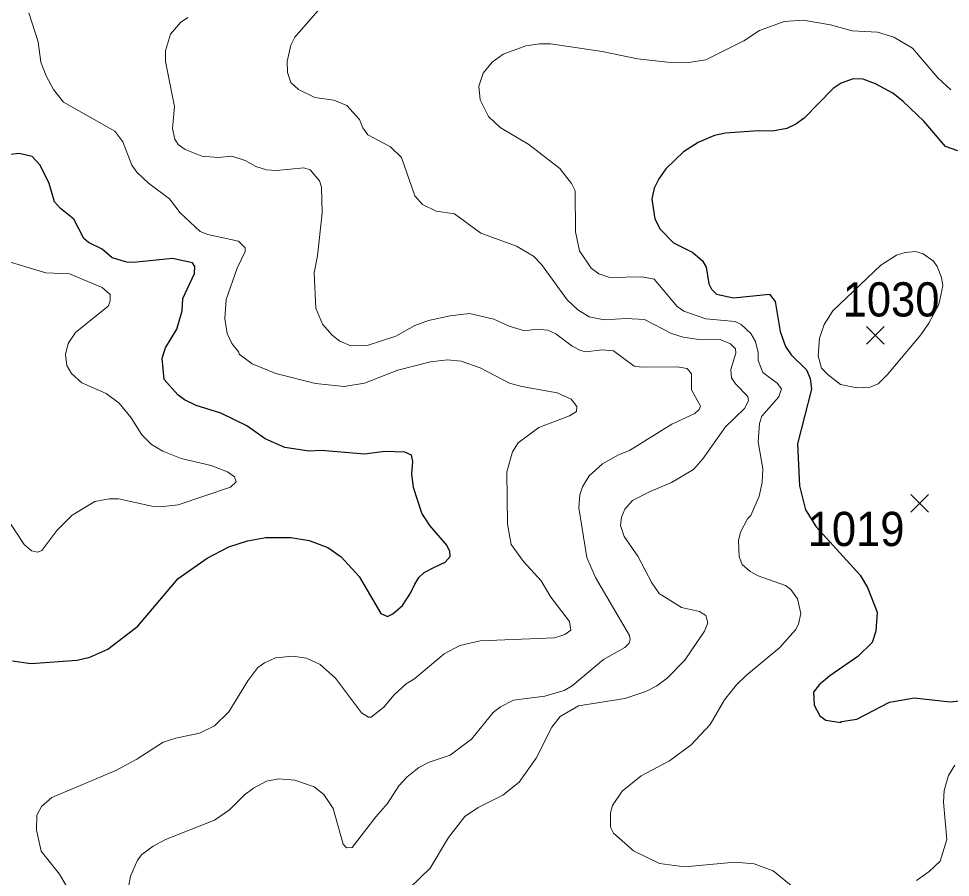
# Model space of a CAD drawing. Extents: x 265 to 291.4, y 7731.5 to 7759.6.
# Drawn here: x 266.78 to 268.956, y 7750.96 to 7752.966 of the extents above; entities that cross this region are included whole.
import ezdxf
from ezdxf.enums import TextEntityAlignment as Align

# ---------------------------------------------------------------- set-up
doc = ezdxf.new("R2010")
doc.units = 0
doc.header["$LTSCALE"] = 0.032
for name, color, linetype, lineweight in [('1', 7, 'Continuous', 25), ('2', 7, 'Continuous', 13), ('21', 7, 'Continuous', 25), ('61', 7, 'Continuous', 13)]:
    doc.layers.add(name, color=color, linetype=linetype, lineweight=lineweight)

msp = doc.modelspace()

# ---------------------------------------------------------------- linework, layer by layer
at = {"layer": '1'}
for points in [[(268.9733, 7752.657), (268.9447, 7752.6674), (268.8938, 7752.7262), (268.846, 7752.7724), (268.8214, 7752.7915), (268.7816, 7752.8137), (268.7522, 7752.8241), (268.7291, 7752.8256), (268.7013, 7752.8153), (268.6822, 7752.8026), (268.6146, 7752.7334), (268.5955, 7752.7191), (268.574, 7752.7095), (268.5406, 7752.7031), (268.5072, 7752.7039), (268.4308, 7752.6984), (268.4054, 7752.6928), (268.3672, 7752.6769), (268.333, 7752.6546), (268.2916, 7752.6148), (268.2749, 7752.5918), (268.2645, 7752.5695), (268.259, 7752.5441), (268.2661, 7752.4979), (268.2781, 7752.4741), (268.3091, 7752.4422), (268.3545, 7752.42), (268.3775, 7752.4001), (268.3855, 7752.385), (268.3918, 7752.3468), (268.3982, 7752.3341), (268.4101, 7752.3221), (268.4499, 7752.3134), (268.5334, 7752.3221), (268.5469, 7752.3054), (268.5589, 7752.2354), (268.5708, 7752.2004), (268.5843, 7752.1805), (268.6201, 7752.1455), (268.6289, 7752.1256), (268.6321, 7752.1002), (268.5994, 7751.9729), (268.6034, 7751.8743), (268.6174, 7751.819), (268.643, 7751.7791), (268.7458, 7751.6659), (268.7625, 7751.6372), (268.7848, 7751.5799), (268.7824, 7751.5354), (268.7736, 7751.5091), (268.7403, 7751.4757), (268.6742, 7751.4312), (268.6496, 7751.4097), (268.6368, 7751.393), (268.6376, 7751.3627), (268.6511, 7751.3373), (268.6655, 7751.327), (268.7005, 7751.3222), (268.7021, 7751.3246), (268.7379, 7751.3301), (268.8142, 7751.3691), (268.8715, 7751.3795), (268.9558, 7751.3699), (268.99, 7751.3739)], [(267.1859, 7752.3953), (267.139, 7752.4056), (267.0483, 7752.3961), (267.0324, 7752.3969), (266.9981, 7752.4072), (266.9751, 7752.4271), (266.9433, 7752.443), (266.9321, 7752.4526), (266.909, 7752.4971), (266.8772, 7752.5226), (266.8637, 7752.5377), (266.851, 7752.5807), (266.8303, 7752.6236), (266.8112, 7752.6435), (266.781, 7752.6506), (266.6983, 7752.6411)], [(267.123, 7752.1972), (267.1493, 7752.2402), (267.162, 7752.2832), (267.1636, 7752.3118), (267.1906, 7752.3707), (267.1914, 7752.3866), (267.1859, 7752.3953)], [(266.7651, 7751.4662), (266.808, 7751.4598), (266.9162, 7751.4678), (266.9464, 7751.4749), (266.9878, 7751.4932), (267.0586, 7751.5473), (267.1525, 7751.6579), (267.2201, 7751.7056), (267.271, 7751.7319), (267.314, 7751.7462), (267.3569, 7751.7541), (267.4158, 7751.7541), (267.4587, 7751.747), (267.5017, 7751.7303), (267.5335, 7751.7088), (267.5749, 7751.6627), (267.6256, 7751.5766), (267.6411, 7751.5698), (267.654, 7751.5755), (267.6767, 7751.5951), (267.6948, 7751.6241), (267.7051, 7751.6447), (267.7144, 7751.6607), (267.7268, 7751.6726), (267.751, 7751.685), (267.7763, 7751.6963), (267.7881, 7751.7096), (267.7873, 7751.7215), (267.7801, 7751.7359), (267.7403, 7751.782), (267.7212, 7751.8106), (267.7021, 7751.8711), (267.6982, 7751.9029), (267.7005, 7751.9316), (267.6974, 7751.9459), (267.6815, 7751.953), (267.6353, 7751.9546), (267.5876, 7751.949), (267.4874, 7751.957), (267.4587, 7751.9554), (267.4015, 7751.9641), (267.3553, 7751.9848), (267.3131, 7752.0151), (267.2519, 7752.0445), (267.1946, 7752.062), (267.1676, 7752.0755), (267.1517, 7752.0874), (267.1198, 7752.1232), (267.1151, 7752.1726), (267.123, 7752.1972)]]:
    msp.add_lwpolyline(points, dxfattribs=at)
at = {"layer": '2'}
for points in [[(267.407, 7752.8654), (267.4158, 7752.9036), (267.4253, 7752.9227), (267.4842, 7752.9903)], [(267.3251, 7752.1598), (267.2949, 7752.1821), (267.2941, 7752.1869), (267.2774, 7752.2068), (267.267, 7752.2307), (267.2615, 7752.2657), (267.2646, 7752.3102), (267.2901, 7752.3834), (267.3092, 7752.4216), (267.3092, 7752.4303), (267.2933, 7752.4462), (267.2217, 7752.4613), (267.2042, 7752.4685), (267.1572, 7752.5122), (267.1318, 7752.5449), (267.0833, 7752.5814), (267.0562, 7752.6069), (267.0443, 7752.6236), (267.0228, 7752.6777), (267.0045, 7752.7032), (266.8844, 7752.7708), (266.8613, 7752.8002), (266.8438, 7752.832), (266.8319, 7752.8639), (266.8255, 7752.9116), (266.8033, 7752.9792)], [(267.446, 7752.6172), (267.3824, 7752.6109), (267.3585, 7752.6125), (267.3338, 7752.6204), (267.3092, 7752.6347), (267.2774, 7752.6443), (267.2456, 7752.6411), (267.2074, 7752.6443), (267.1684, 7752.6602), (267.1525, 7752.6721), (267.1445, 7752.6841), (267.1389, 7752.7095), (267.1437, 7752.7604), (267.123, 7752.8654), (267.123, 7752.8909), (267.1342, 7752.9299), (267.158, 7752.9569), (267.1747, 7752.9681)], [(268.1619, 7751.1106), (268.1667, 7751.1281), (268.1898, 7751.1615), (268.2335, 7751.1973), (268.3004, 7751.2323), (268.3505, 7751.2697), (268.395, 7751.3174), (268.4284, 7751.3747), (268.4563, 7751.4097), (268.4801, 7751.4328), (268.5581, 7751.4972), (268.5947, 7751.5386), (268.601, 7751.5513), (268.6066, 7751.5768), (268.5994, 7751.611), (268.5835, 7751.6324), (268.5708, 7751.642), (268.5072, 7751.6643), (268.4881, 7751.6746), (268.4698, 7751.6913), (268.4626, 7751.7088), (268.461, 7751.747), (268.4658, 7751.7661), (268.4825, 7751.7979), (268.4897, 7751.805), (268.5096, 7751.8504), (268.5167, 7751.8822), (268.5183, 7751.914), (268.5072, 7751.9777), (268.5104, 7752.0206), (268.5159, 7752.0373), (268.5557, 7752.0827), (268.5613, 7752.101), (268.5517, 7752.1145), (268.5183, 7752.1392), (268.5072, 7752.167), (268.5072, 7752.1861), (268.5008, 7752.2116), (268.4897, 7752.2307), (268.4674, 7752.2513), (268.4531, 7752.2585), (268.3847, 7752.2648), (268.3338, 7752.2823), (268.3178, 7752.2935), (268.2646, 7752.3571), (268.2351, 7752.3627), (268.1604, 7752.3611), (268.1349, 7752.3698), (268.1174, 7752.3834), (268.0895, 7752.4232), (268.0808, 7752.4677), (268.08, 7752.5639), (268.0713, 7752.5807), (268.0442, 7752.6157), (267.9718, 7752.6721), (267.9042, 7752.7119), (267.8772, 7752.7374), (267.8581, 7752.7764), (267.8549, 7752.8082), (267.8652, 7752.8384), (267.8859, 7752.8638), (267.9114, 7752.8829), (267.9647, 7752.902), (267.9965, 7752.9068), (268.0219, 7752.9068), (268.1429, 7752.8893), (268.2256, 7752.8718), (268.2956, 7752.8638), (268.3401, 7752.8623), (268.3847, 7752.8694), (268.4738, 7752.914), (268.5104, 7752.9378), (268.5676, 7752.9593), (268.6122, 7752.9625), (268.6758, 7752.9514), (268.7267, 7752.937), (268.7856, 7752.9339), (268.8238, 7752.9227), (268.8675, 7752.8965), (268.9272, 7752.8273), (268.9574, 7752.7994)], [(267.5462, 7752.7628), (267.516, 7752.7756), (267.4715, 7752.7819), (267.4333, 7752.8002), (267.4158, 7752.8169), (267.4078, 7752.84), (267.407, 7752.8654)], [(267.6934, 7750.9356), (267.7411, 7750.9817), (267.7841, 7751.0533), (267.8223, 7751.1027), (267.8533, 7751.1233), (267.9106, 7751.152), (267.9488, 7751.1822), (267.9885, 7751.2387), (268.0251, 7751.3111), (268.045, 7751.3357), (268.0872, 7751.3612), (268.1954, 7751.3779), (268.2447, 7751.3946), (268.2701, 7751.4073), (268.2948, 7751.4256), (268.3362, 7751.4678), (268.3815, 7751.5354), (268.3894, 7751.5545), (268.3847, 7751.572), (268.3704, 7751.5815), (268.3282, 7751.5903), (268.2757, 7751.6229), (268.259, 7751.6484), (268.2264, 7751.7104), (268.1938, 7751.7565), (268.1858, 7751.782), (268.1882, 7751.8011), (268.1961, 7751.8202), (268.2137, 7751.8401), (268.255, 7751.8615), (268.3051, 7751.8822), (268.356, 7751.9132), (268.3783, 7751.9379), (268.4308, 7752.0127), (268.4754, 7752.0556), (268.4849, 7752.0731), (268.4833, 7752.0835), (268.4539, 7752.1129), (268.4451, 7752.1272), (268.4435, 7752.1463), (268.4547, 7752.1845), (268.4539, 7752.1948), (268.4427, 7752.206), (268.4197, 7752.2155), (268.3688, 7752.2163), (268.3322, 7752.2219), (268.3051, 7752.2306), (268.2415, 7752.2633), (268.1985, 7752.2656), (268.1476, 7752.2625), (268.1126, 7752.2696), (268.0856, 7752.2855), (268.0609, 7752.3094), (268.0012, 7752.3913), (267.9822, 7752.4112), (267.9424, 7752.4343), (267.8597, 7752.4645), (267.7976, 7752.5099), (267.7547, 7752.5162), (267.7228, 7752.5321), (267.7053, 7752.552), (267.6743, 7752.6411), (267.6481, 7752.6666), (267.5955, 7752.6944), (267.5836, 7752.7111), (267.5757, 7752.7302), (267.5462, 7752.7628)], [(267.4699, 7752.3722), (267.4778, 7752.412), (267.489, 7752.5123), (267.4874, 7752.5719), (267.4826, 7752.587), (267.4611, 7752.6125), (267.446, 7752.6172)], [(266.7476, 7752.4009), (266.843, 7752.3722), (266.8987, 7752.3699), (266.9751, 7752.338), (266.9934, 7752.3213), (266.9934, 7752.3062), (266.9886, 7752.2943), (266.913, 7752.233), (266.8955, 7752.2068), (266.8892, 7752.1813), (266.8923, 7752.1559), (266.9035, 7752.1368), (266.9274, 7752.1153), (266.9846, 7752.0906), (267.0149, 7752.0676), (267.0427, 7752.0334)], [(267.0363, 7750.9372), (267.0411, 7750.9627), (267.0578, 7751.0008), (267.0674, 7751.0136), (267.0944, 7751.0334), (267.123, 7751.0486), (267.2376, 7751.0939), (267.2726, 7751.1177), (267.3076, 7751.1528), (267.3283, 7751.1687), (267.3585, 7751.1846), (267.3871, 7751.1901), (267.4253, 7751.187), (267.4699, 7751.1718), (267.4929, 7751.1536), (267.5144, 7751.1209), (267.5375, 7751.0374), (267.5454, 7751.0295), (267.559, 7751.0303), (267.6138, 7751.1019), (267.6417, 7751.1329), (267.6679, 7751.1742), (267.687, 7751.1949), (267.7149, 7751.2172), (267.7388, 7751.2291), (267.7881, 7751.2458), (267.8374, 7751.2832), (267.8883, 7751.3453), (267.905, 7751.3588), (267.936, 7751.3739), (268.0092, 7751.3834), (268.0538, 7751.397), (268.0729, 7751.4073), (268.146, 7751.4694), (268.1954, 7751.4972), (268.2057, 7751.5075), (268.2081, 7751.5147), (268.2065, 7751.5251), (268.1269, 7751.6603), (268.1071, 7751.7072), (268.088, 7751.8234), (268.0903, 7751.8536), (268.0967, 7751.8727), (268.1126, 7751.8981), (268.1436, 7751.926), (268.181, 7751.9467), (268.2065, 7751.957), (268.3059, 7752.019), (268.3592, 7752.0437), (268.3696, 7752.0532), (268.3727, 7752.0604), (268.3513, 7752.0986), (268.3513, 7752.136), (268.3417, 7752.1487), (268.3179, 7752.1527), (268.2351, 7752.1519), (268.2176, 7752.1543), (268.1691, 7752.1901), (268.1429, 7752.1925), (268.1047, 7752.1877), (268.0919, 7752.1909), (268.0729, 7752.2012), (268.0347, 7752.2298), (268.0156, 7752.2386), (267.9901, 7752.2402), (267.9615, 7752.237), (267.9257, 7752.2473), (267.8899, 7752.2641), (267.8326, 7752.2768), (267.7881, 7752.272), (267.7372, 7752.2609), (267.7053, 7752.2489), (267.6608, 7752.2243), (267.594, 7752.2028), (267.5558, 7752.202), (267.5303, 7752.2123), (267.512, 7752.2267), (267.4898, 7752.2521), (267.4738, 7752.2895), (267.4699, 7752.3722)], [(266.9035, 7750.9197), (266.8756, 7750.9674), (266.8327, 7751.0215), (266.8215, 7751.0708), (266.8223, 7751.1058), (266.8335, 7751.1257), (266.8574, 7751.1464), (267.0069, 7751.21), (267.0562, 7751.2363), (267.1175, 7751.2761), (267.1469, 7751.2856), (267.2026, 7751.2967), (267.2376, 7751.3142), (267.271, 7751.3469), (267.3155, 7751.4193), (267.3386, 7751.4503), (267.3537, 7751.4614), (267.38, 7751.4733), (267.4206, 7751.4765), (267.4524, 7751.4725), (267.4842, 7751.4574), (267.52, 7751.4256), (267.5804, 7751.3445), (267.5972, 7751.3341), (267.6035, 7751.3341), (267.6329, 7751.358), (267.6568, 7751.3866), (267.6847, 7751.4121), (267.7053, 7751.4248), (267.7737, 7751.4821), (267.8103, 7751.502), (267.8581, 7751.5123), (268.0315, 7751.5195), (268.0554, 7751.5274), (268.0697, 7751.5378), (268.0665, 7751.5577), (268.0227, 7751.6149), (268.0005, 7751.6531), (267.9591, 7751.6977), (267.9304, 7751.7375), (267.9217, 7751.7852), (267.9201, 7751.9077), (267.9336, 7751.9538), (267.9464, 7751.9753), (267.9949, 7752.0111), (268.0665, 7752.0381), (268.0832, 7752.0485), (268.084, 7752.0596), (268.0705, 7752.0771), (268.0379, 7752.0922), (267.9551, 7752.1065), (267.9265, 7752.1145), (267.8581, 7752.1503), (267.8135, 7752.1662), (267.7817, 7752.1686), (267.7419, 7752.1646)], [(267.7419, 7752.1646), (267.6656, 7752.1447), (267.5876, 7752.1145), (267.5399, 7752.1065), (267.4731, 7752.1137), (267.3808, 7752.1368), (267.3251, 7752.1598)], [(267.0427, 7752.0334), (267.0673, 7751.9936), (267.0904, 7751.9713), (267.1167, 7751.9554), (267.1596, 7751.9387), (267.2296, 7751.922), (267.2678, 7751.9077)], [(267.2678, 7751.9077), (267.2837, 7751.8957), (267.2877, 7751.8838), (267.275, 7751.8719), (267.1525, 7751.8305), (267.1175, 7751.8265), (267.0912, 7751.8273), (267.0133, 7751.844), (266.991, 7751.844), (266.9576, 7751.8377), (266.9051, 7751.8058), (266.8693, 7751.7701), (266.8343, 7751.7239), (266.8247, 7751.7199), (266.8096, 7751.7231), (266.7929, 7751.7374), (266.7261, 7751.8377)], [(268.9662, 7751.222), (268.9519, 7751.1981), (268.9415, 7751.1631), (268.9399, 7751.1361), (268.9479, 7751.0486), (268.932, 7750.9977), (268.9065, 7750.9738), (268.8771, 7750.9531)], [(268.6186, 7750.9133), (268.5422, 7750.9754), (268.4976, 7750.9921), (268.4531, 7750.9961), (268.3354, 7750.9849), (268.2765, 7750.9929), (268.216, 7751.0223), (268.1691, 7751.0637), (268.1619, 7751.0772), (268.1619, 7751.1106)]]:
    msp.add_lwpolyline(points, dxfattribs=at)
msp.add_lwpolyline([(268.7936, 7752.3897), (268.8302, 7752.4136), (268.8508, 7752.42), (268.8747, 7752.4216), (268.8922, 7752.4168), (268.9169, 7752.3993), (268.9256, 7752.3866), (268.9352, 7752.3611), (268.9383, 7752.342), (268.9292, 7752.2979), (268.906, 7752.2548), (268.8874, 7752.2275), (268.8095, 7752.1344), (268.7872, 7752.1129), (268.7689, 7752.105), (268.7379, 7752.1034), (268.6997, 7752.1113), (268.6703, 7752.1336), (268.6551, 7752.1495), (268.6472, 7752.1782), (268.6504, 7752.2195), (268.6615, 7752.2513), (268.6814, 7752.2832)], close=True, dxfattribs=at)
at = {"layer": '21'}
for p, q in [((268.7602, 7752.2468), (268.8014, 7752.2056)), ((268.8014, 7752.2468), (268.7602, 7752.2056)), ((268.8638, 7751.8545), (268.905, 7751.8133)), ((268.905, 7751.8545), (268.8638, 7751.8133))]:
    msp.add_line(p, q, dxfattribs=at)

# ---------------------------------------------------------------- texts
at = {"layer": '61', "width": 0.95}
for s, p in [('1030', (268.8176, 7752.2701)), ('1019', (268.7359, 7751.734))]:
    msp.add_text(s, height=0.08, dxfattribs=at).set_placement(p, align=Align.CENTER)

doc.saveas('drawing.dxf')
